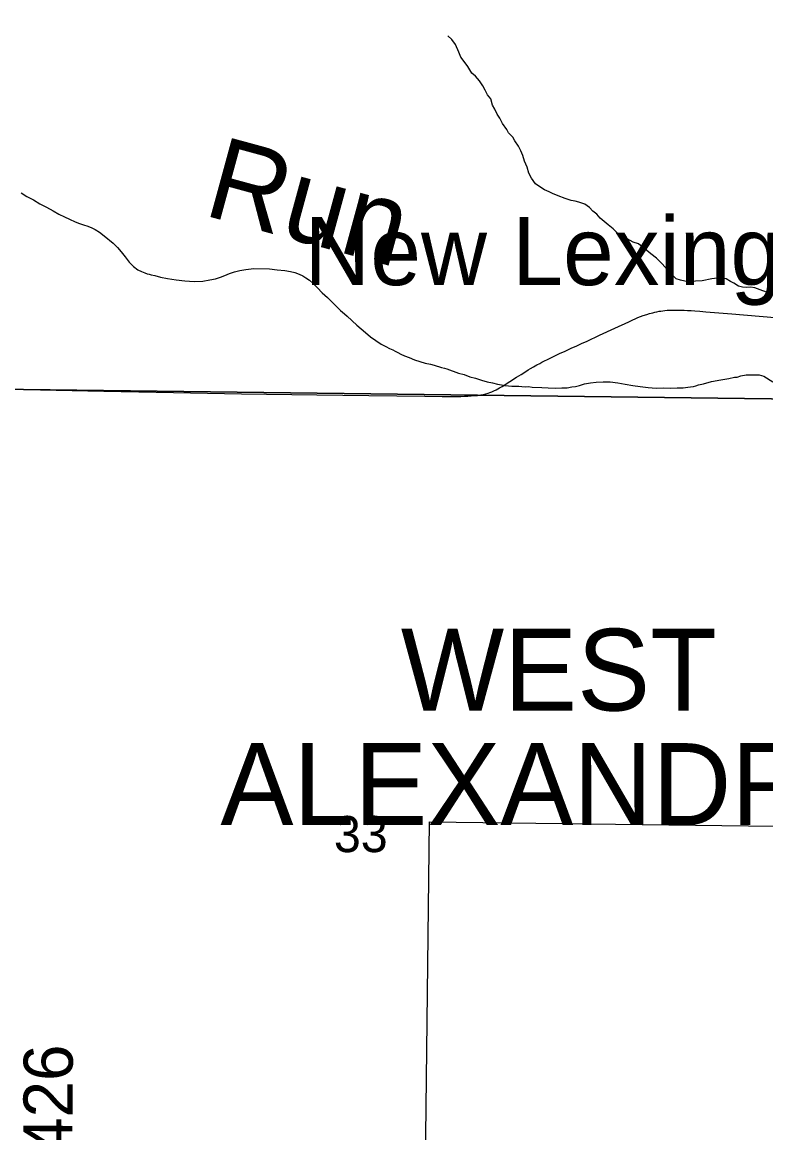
# Model space of a CAD drawing. Extents: x 0 to 34, y 0 to 22.
# Drawn here: x 28.088 to 28.518, y 18.399 to 19.042 of the extents above; entities that cross this region are included whole.
import ezdxf

# ---------------------------------------------------------------- set-up
doc = ezdxf.new("R2010")
doc.units = 0
for name, color, linetype in [('GM_X_Corporation', 7, 'Continuous'), ('GM_X_Corporation_Text', 7, 'Continuous'), ('GM_X_County_Road', 7, 'Continuous'), ('GM_X_Minor_River', 7, 'Continuous'), ('GM_X_Minor_River_Text', 7, 'Continuous'), ('GM_X_Section', 7, 'Continuous'), ('GM_X_Section_Text', 7, 'Continuous'), ('GM_X_Township_Road_Text', 7, 'Continuous'), ('GM_X_Unincorporated_Text', 7, 'Continuous')]:
    doc.layers.add(name, color=color, linetype=linetype)

msp = doc.modelspace()

# ---------------------------------------------------------------- linework, layer by layer
at = {"layer": 'GM_X_Corporation'}
msp.add_lwpolyline([(28.32088, 18.36386), (28.32328, 18.57864), (28.52331, 18.57601)], dxfattribs=at)
at = {"layer": 'GM_X_County_Road'}
msp.add_lwpolyline([(28.07216, 18.82908), (28.089, 18.82884), (28.13487, 18.82789), (28.17527, 18.82707), (28.21456, 18.82641), (28.25821, 18.82575), (28.28814, 18.82547), (28.32056, 18.82497), (28.33067, 18.82481), (28.33684, 18.82481), (28.33927, 18.82481), (28.34152, 18.82485), (28.34366, 18.82493), (28.34559, 18.82502), (28.34744, 18.82514), (28.34942, 18.8253), (28.35102, 18.82547), (28.35296, 18.82575), (28.35443, 18.82604), (28.35596, 18.82639), (28.35719, 18.82674), (28.3583, 18.82708), (28.35932, 18.82748), (28.36055, 18.82801), (28.36191, 18.82872), (28.36294, 18.82925), (28.3638, 18.82975), (28.3654, 18.83069), (28.36984, 18.83357), (28.37375, 18.83603), (28.3763, 18.83763), (28.37839, 18.83895), (28.38041, 18.84018), (28.3818, 18.841), (28.38357, 18.84199), (28.3855, 18.8431), (28.3871, 18.84396), (28.38838, 18.84466), (28.38978, 18.8454), (28.39154, 18.84631), (28.39348, 18.84729), (28.39582, 18.8484), (28.39857, 18.84968), (28.40174, 18.85112), (28.40535, 18.85276), (28.40856, 18.85424), (28.41127, 18.85547), (28.41448, 18.85691), (28.42171, 18.86024), (28.43047, 18.86431), (28.43861, 18.86809), (28.44062, 18.86899), (28.44271, 18.86994), (28.44395, 18.87047), (28.44539, 18.87105), (28.44703, 18.87166), (28.44905, 18.87232), (28.45065, 18.87282), (28.45246, 18.87331), (28.45377, 18.87364), (28.45492, 18.87389), (28.45615, 18.87413), (28.45718, 18.8743), (28.45834, 18.87446), (28.4594, 18.87458), (28.46088, 18.87471), (28.46224, 18.87479), (28.4638, 18.87483), (28.46536, 18.87487), (28.46692, 18.87487), (28.46877, 18.87483), (28.47071, 18.87475), (28.47268, 18.87467), (28.47469, 18.87454), (28.47691, 18.87438), (28.47966, 18.87417), (28.48316, 18.87389), (28.49831, 18.87261), (28.51407, 18.87129), (28.53458, 18.86953)], dxfattribs=at)
at = {"layer": 'GM_X_Minor_River'}
for points in [[(28.49947, 18.89047), (28.4974, 18.89148), (28.49497, 18.89287), (28.49119, 18.89353), (28.48661, 18.89289), (28.48106, 18.8917), (28.47726, 18.8916), (28.47441, 18.89149), (28.47099, 18.89157), (28.46853, 18.8922), (28.46608, 18.89303), (28.46404, 18.89479), (28.462, 18.89693), (28.46035, 18.89906), (28.4572, 18.90237), (28.45461, 18.90491), (28.45144, 18.90746), (28.44902, 18.90942), (28.4466, 18.91119), (28.44418, 18.91315), (28.44116, 18.91418), (28.4376, 18.91617), (28.43498, 18.91756), (28.43236, 18.91915), (28.42958, 18.92188), (28.42679, 18.92423), (28.42437, 18.92619), (28.42214, 18.92815), (28.4201, 18.93029), (28.41787, 18.93206), (28.41583, 18.9342), (28.41322, 18.93617), (28.40964, 18.9374), (28.40756, 18.93783), (28.40529, 18.93827), (28.40172, 18.9395), (28.39776, 18.94093), (28.39457, 18.94234), (28.3925, 18.94334), (28.38987, 18.94455), (28.38706, 18.94614), (28.38464, 18.94791), (28.38225, 18.9512), (28.38081, 18.95409), (28.37976, 18.95753), (28.37832, 18.96099), (28.37727, 18.96444), (28.3762, 18.96713), (28.37475, 18.96982), (28.37274, 18.97291), (28.37147, 18.97504), (28.36906, 18.97738), (28.36797, 18.97949), (28.36558, 18.98279), (28.36395, 18.98587), (28.36249, 18.98819), (28.36105, 18.99126), (28.35978, 18.99357), (28.35874, 18.99721), (28.35689, 18.99954), (28.35544, 19.00223), (28.35418, 19.00474), (28.35216, 19.00764), (28.34995, 19.01035), (28.3479, 19.01193), (28.34553, 19.01579), (28.34333, 19.01869), (28.34149, 19.02121), (28.34023, 19.02409), (28.33845, 19.0287), (28.33625, 19.0316), (28.33402, 19.03356)], [(28.08699, 18.94265), (28.09036, 18.94065), (28.09411, 18.93865), (28.09785, 18.93645), (28.10178, 18.93444), (28.10552, 18.93224), (28.10889, 18.93044), (28.11208, 18.92883), (28.11508, 18.92741), (28.11827, 18.92599), (28.12071, 18.92498), (28.12316, 18.92415), (28.12561, 18.92351), (28.12786, 18.9225), (28.12992, 18.92149), (28.13235, 18.9199), (28.13515, 18.91792), (28.14036, 18.91359), (28.14276, 18.91105), (28.14497, 18.90851), (28.14718, 18.90559), (28.14957, 18.90266), (28.15198, 18.90012), (28.15459, 18.89815), (28.15665, 18.89714), (28.15853, 18.89633), (28.16003, 18.8959), (28.16117, 18.89568), (28.16229, 18.89527), (28.16437, 18.89484), (28.16758, 18.89399), (28.17173, 18.89312), (28.17664, 18.89242), (28.18175, 18.89171), (28.18724, 18.89138), (28.19218, 18.89163), (28.19618, 18.89229), (28.19942, 18.89297)], [(28.19942, 18.89297), (28.20229, 18.89385), (28.20497, 18.89492), (28.20766, 18.896), (28.21053, 18.89707), (28.21358, 18.89775), (28.21701, 18.89842), (28.22158, 18.89888), (28.23068, 18.89864), (28.23522, 18.89814), (28.23958, 18.89784), (28.24297, 18.89718), (28.24542, 18.89654), (28.24787, 18.89571), (28.25012, 18.8947), (28.2518, 18.89351), (28.25385, 18.89212), (28.25608, 18.89016), (28.25849, 18.88781), (28.26127, 18.88487), (28.26423, 18.88212), (28.26701, 18.87938), (28.26942, 18.87684), (28.27183, 18.87468), (28.27406, 18.87271), (28.27573, 18.87133), (28.28129, 18.86604), (28.28371, 18.86406), (28.28632, 18.8619), (28.2891, 18.85935), (28.29227, 18.85717), (28.29526, 18.85518), (28.29807, 18.85377), (28.30013, 18.85257), (28.30219, 18.85176), (28.30351, 18.85115), (28.30501, 18.85035), (28.30669, 18.84935), (28.30894, 18.84834), (28.31157, 18.84731), (28.31458, 18.84609), (28.31778, 18.84506), (28.32079, 18.84421), (28.32381, 18.84356), (28.32607, 18.84293), (28.33022, 18.84168), (28.33191, 18.84126), (28.33342, 18.84083), (28.34019, 18.83837), (28.34339, 18.83752), (28.34659, 18.83629), (28.34998, 18.83544), (28.35337, 18.83421), (28.35676, 18.83336), (28.35978, 18.83271), (28.36261, 18.83187), (28.36488, 18.83162), (28.36695, 18.83119), (28.36904, 18.83094), (28.37093, 18.83089), (28.37491, 18.83079), (28.3768, 18.83055), (28.3787, 18.8305), (28.3806, 18.83064), (28.38268, 18.83021), (28.38837, 18.83006), (28.39196, 18.82978), (28.39613, 18.82967), (28.39993, 18.82976), (28.40297, 18.82987), (28.40564, 18.83038), (28.40773, 18.83051), (28.41002, 18.83122), (28.41308, 18.83209), (28.41651, 18.83277), (28.41974, 18.83306), (28.42373, 18.83334), (28.4279, 18.83323), (28.43226, 18.83274), (28.4366, 18.83205), (28.44094, 18.83118), (28.4453, 18.83068), (28.44983, 18.82999), (28.45438, 18.82969), (28.45874, 18.82976), (28.46291, 18.82966), (28.46671, 18.82975), (28.47013, 18.82985), (28.47279, 18.83016), (28.47432, 18.8305), (28.47603, 18.83065), (28.47737, 18.831), (28.4789, 18.83153), (28.48176, 18.83222), (28.48653, 18.83343), (28.49187, 18.83444), (28.49644, 18.83527), (28.49987, 18.83595), (28.50139, 18.8361), (28.5035, 18.83681), (28.50655, 18.8373)], [(28.51834, 18.88525), (28.51457, 18.88648), (28.51156, 18.8877), (28.5091, 18.88814), (28.50701, 18.888), (28.50435, 18.88807), (28.50208, 18.8887), (28.49947, 18.89047)], [(28.50655, 18.8373), (28.50958, 18.83741), (28.51243, 18.83734), (28.51413, 18.8373), (28.51546, 18.83707), (28.51678, 18.83666), (28.52201, 18.83328)]]:
    msp.add_lwpolyline(points, dxfattribs=at)
at = {"layer": 'GM_X_Section'}
for points in [[(28.07768, 19.33287), (28.58827, 19.32216), (28.58291, 18.82262), (28.07279, 18.82897)], [(28.07279, 18.82897), (28.58291, 18.82262), (28.57207, 18.32532), (28.07507, 18.33367), (28.06617, 18.33388)]]:
    msp.add_lwpolyline(points, close=True, dxfattribs=at)

# ---------------------------------------------------------------- texts
at = {"layer": 'GM_X_Corporation_Text'}
for s, p in [('WEST', (28.30674, 18.64297)), ('ALEXANDRIA', (28.20236, 18.57679))]:
    msp.add_text(s, height=0.047348, rotation=0.00001, dxfattribs=at).set_placement(p)
at = {"layer": 'GM_X_Minor_River_Text'}
msp.add_text('Run', height=0.047348, rotation=344.74838, dxfattribs=at).set_placement((28.19155, 18.9301))
at = {"layer": 'GM_X_Section_Text'}
msp.add_text('33', height=0.020928, rotation=0.00001, dxfattribs=at).set_placement((28.26799, 18.56102))
at = {"layer": 'GM_X_Township_Road_Text'}
msp.add_text('T-426', height=0.028409, rotation=89.71875, dxfattribs=at).set_placement((28.11647, 18.35033))
at = {"layer": 'GM_X_Unincorporated_Text'}
msp.add_text('New Lexington', height=0.0394886, rotation=0.00001, dxfattribs=at).set_placement((28.25091, 18.8893))

doc.saveas('drawing.dxf')
